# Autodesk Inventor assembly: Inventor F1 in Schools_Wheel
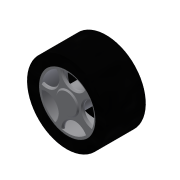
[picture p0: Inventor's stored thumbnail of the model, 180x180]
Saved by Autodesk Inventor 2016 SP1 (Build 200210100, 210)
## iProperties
Created: 2015-12
Part Number: Inventor F1 in Schools_Wheel
Document SubType Name: Assembly
Designer: Autodesk Inc.
Author: Autodesk Inc
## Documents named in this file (3)
- D:\F1 2016\F1 Inventor Tutorial\Data Sets\Inventor F1 in Schools_Wheel.iam
- D:\F1 2016\F1 Inventor Tutorial\Data Sets\Inventor F1 in Schools_Hub.ipt
- D:\F1 2016\F1 Inventor Tutorial\Data Sets\Inventor F1 in Schools_Wheel.ipt
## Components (2 placed, 2 different names)
1. Inventor F1 in Schools_Hub:1 — Mate:1, Mate:2
2. Inventor F1 in Schools_Wheel:1 — Mate:1, Mate:2
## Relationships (2: Mate 2)
- Mate:1: Inventor F1 in Schools_Hub:1 ↔ Inventor F1 in Schools_Wheel:1
- Mate:2: Inventor F1 in Schools_Hub:1 ↔ Inventor F1 in Schools_Wheel:1
